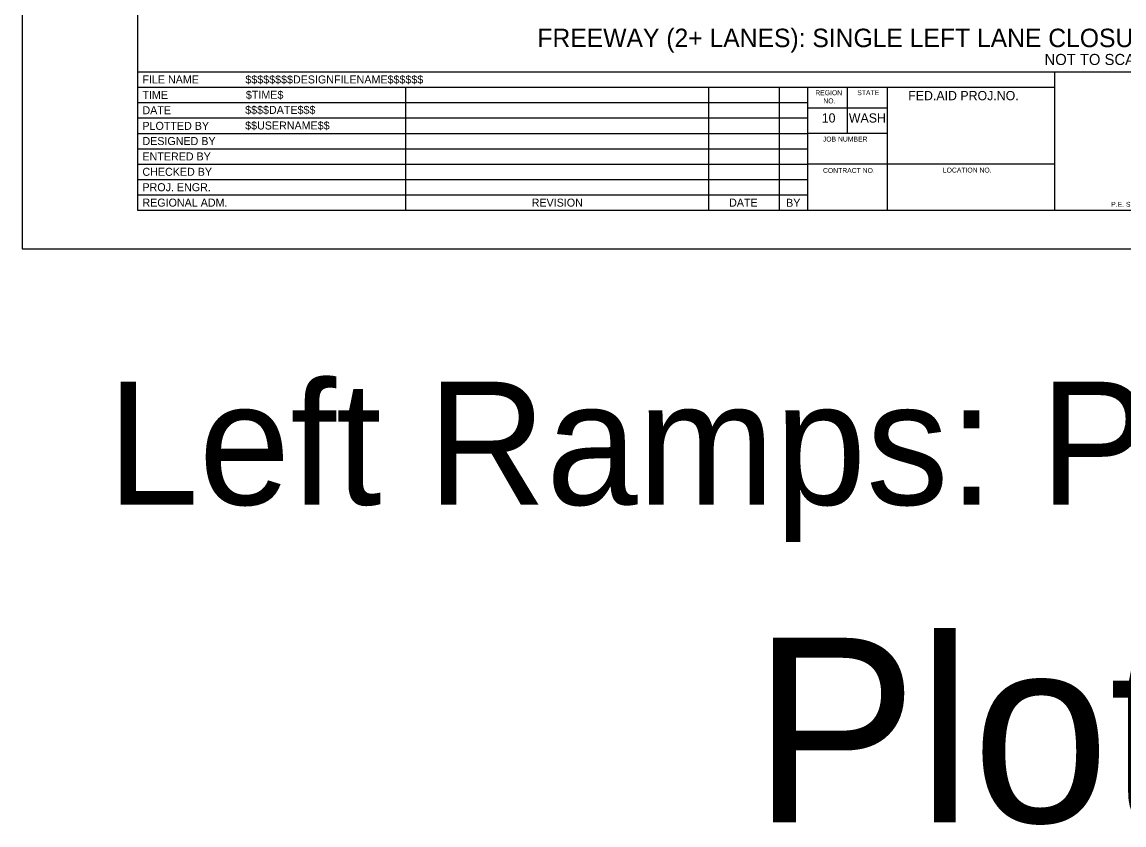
# Model space of a CAD drawing. Extents: x 99999 to 100116, y 99995 to 100013.
# Drawn here: x 100059.06 to 100068.02, y 99995.01 to 100001.53 of the extents above; entities that cross this region are included whole.
import ezdxf

# ---------------------------------------------------------------- set-up
doc = ezdxf.new("R2010")
doc.units = 0
for name, color, linetype in [('SH_DE_DetailHeading1Text', 7, 'Continuous'), ('SH_GI_PlotLimits', 7, 'Continuous'), ('SH_GI_SheetBorder', 7, 'Continuous'), ('SH_GI_SheetLocationText', 7, 'Continuous'), ('SH_GI_SheetTextInCells', 7, 'Continuous'), ('SH_GI_TitleBlockText', 7, 'Continuous')]:
    doc.layers.add(name, color=color, linetype=linetype)

msp = doc.modelspace()

# ---------------------------------------------------------------- linework, layer by layer
at = {"layer": 'SH_GI_PlotLimits'}
msp.add_lwpolyline([(100059.0625, 99999.6875), (100076.0625, 99999.6875), (100076.0625, 100010.6875), (100059.0625, 100010.6875)], close=True, dxfattribs=at)
at = {"layer": 'SH_GI_SheetBorder'}
for p, q in [((100060, 100010.375), (100060, 100000)), ((100060, 100001.1259), (100075.75, 100001.1259)), ((100067.4566, 100000), (100067.4566, 100001.1259)), ((100060, 100001.0008), (100067.4566, 100001.0008)), ((100062.179, 100001.0008), (100062.179, 100000)), ((100064.641, 100001.0008), (100064.641, 100000)), ((100065.2164, 100001.0008), (100065.2164, 100000)), ((100065.4451, 100001.0008), (100065.4451, 100000)), ((100065.7719, 100000.6255), (100065.7719, 100001.0008)), ((100066.0956, 100000), (100066.0956, 100001.0008)), ((100060, 100000.8757), (100062.1821, 100000.8757)), ((100062.1821, 100000.8757), (100065.4466, 100000.8757)), ((100066.0958, 100000.831), (100065.4466, 100000.831)), ((100060, 100000.7506), (100062.1821, 100000.7506)), ((100062.1821, 100000.7506), (100065.4466, 100000.7506)), ((100060, 100000.6255), (100065.4466, 100000.6255)), ((100066.0958, 100000.6255), (100065.4466, 100000.6255)), ((100060, 100000.5004), (100065.4466, 100000.5004)), ((100060, 100000.3753), (100065.4466, 100000.3753)), ((100067.4566, 100000.3753), (100065.4466, 100000.3753)), ((100060, 100000.2502), (100065.4466, 100000.2502)), ((100060, 100000.1251), (100065.4466, 100000.1251)), ((100060, 100000), (100075.75, 100000))]:
    msp.add_line(p, q, dxfattribs=at)

# ---------------------------------------------------------------- texts
at = {"layer": 'SH_DE_DetailHeading1Text'}
for s, height, p in [('FREEWAY (2+ LANES): SINGLE LEFT LANE CLOSURE (MAINTAIN EXISTING SPEED LIMIT)', 0.15, (100063.2512, 100001.3259)), ('NOT TO SCALE', 0.09, (100067.3727, 100001.1809))]:
    msp.add_text(s, height=height, rotation=360, dxfattribs=at).set_placement(p)
at = {"layer": 'SH_GI_SheetLocationText'}
for s, height, p in [('Left Ramps: Parallel On-Ramp', 1, (100059.7551, 99997.6071)), ('Plot 4', 1.5, (100065.0007, 99995.0267))]:
    msp.add_text(s, height=height, dxfattribs=at).set_placement(p)
at = {"layer": 'SH_GI_SheetTextInCells'}
for s, height, p in [('FILE NAME', 0.06505, (100060.041, 100001.0308)), ('TIME', 0.06505, (100060.041, 100000.9057)), ('REGION', 0.04003, (100065.5099, 100000.9352)), ('NO.', 0.04003, (100065.5752, 100000.869)), ('STATE', 0.04003, (100065.8511, 100000.9357)), ('FED.AID PROJ.NO.', 0.07506, (100066.2652, 100000.8945)), ('DATE', 0.06505, (100060.041, 100000.7806)), ('10', 0.07506, (100065.5621, 100000.7131)), ('WASH', 0.07506, (100065.7826, 100000.7131)), ('PLOTTED BY', 0.06505, (100060.041, 100000.6538)), ('DESIGNED BY', 0.065052, (100060.041, 100000.5304)), ('JOB NUMBER', 0.04003, (100065.5712, 100000.5587)), ('ENTERED BY', 0.06505, (100060.041, 100000.4053)), ('CHECKED BY', 0.06505, (100060.041, 100000.2802)), ('CONTRACT NO.', 0.040032, (100065.5725, 100000.3037)), ('LOCATION NO.', 0.040032, (100066.5465, 100000.3067)), ('PROJ. ENGR.', 0.065052, (100060.041, 100000.1551)), ('REGIONAL ADM.', 0.065052, (100060.041, 100000.03)), ('REVISION', 0.06505, (100063.2048, 100000.03)), ('DATE', 0.06505, (100064.8091, 100000.03)), ('BY', 0.06505, (100065.2725, 100000.0285)), ('P.E. STAMP BOX', 0.040032, (100067.915, 100000.0286))]:
    msp.add_text(s, height=height, dxfattribs=at).set_placement(p)
at = {"layer": 'SH_GI_TitleBlockText'}
for s, height, p in [('$$$$$$$$DESIGNFILENAME$$$$$$', 0.065052, (100060.8775, 100001.0308)), ('$TIME$', 0.06505, (100060.882, 100000.9059)), ('$$$$DATE$$$', 0.065052, (100060.8759, 100000.7835)), ('$$USERNAME$$', 0.065052, (100060.8759, 100000.6567))]:
    msp.add_text(s, height=height, dxfattribs=at).set_placement(p)

doc.saveas('drawing.dxf')
